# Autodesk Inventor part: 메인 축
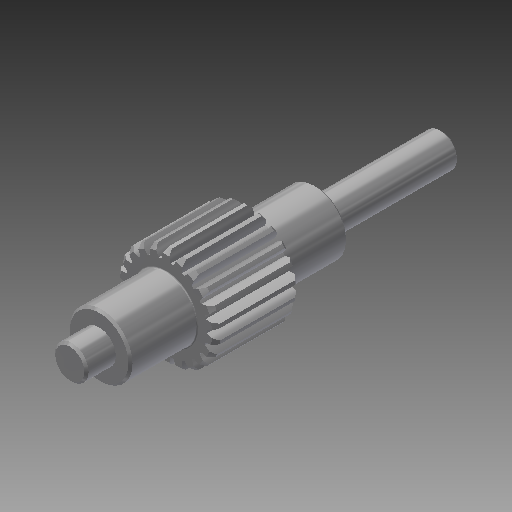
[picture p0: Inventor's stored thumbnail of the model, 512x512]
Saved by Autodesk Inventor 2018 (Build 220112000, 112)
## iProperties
Created: 2016-02
Part Number: 메인 축
Material: 강철, 연강
Document SubType Name: Modeling
Categories: <?xml version="1.0" encoding="UTF-16"?> <MemberInstance><Categories><FamilyTemplate><FamilyTemplateParameter ValueType="xs:double" Id="1" ObjectReferenceKey="da
Density: 7.86 g/cm^3
Appearance: 강철
CustomPartVersion: 1
Author: mdu
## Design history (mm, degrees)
sketch "Sketch1"
  geometry: C1 r 12 at (0, 0)
  constraints: 1 centre point
  dimensions: "d0" = 24 diameter of C1 (= da_da)
extrude "Extrusion1" new body sketch "Sketch1" distance "d1" = 20 (= da_b); taper "d2" = 0 deg
workplane "Work Plane2"
feature "피치 지름" dims "d4" = 10, "d5" = 0
workplane "Work Plane8"
workplane "Work Plane9"
chamfer "모따기1" distance "d49" = 1; stored, may be unused: second distance "d50" = 2, angle "d51" = 45 deg
sketch "스케치3"
  geometry: C1 r 7.5 at (0, 0); 1 further point
  constraints: 1 centre point, 1 coincident
  dimensions: "d52" = 15 diameter of C1
extrude "돌출2" join sketch "스케치3" distance "d53" = 16; taper "d54" = 0 deg
sketch "스케치4"
  geometry: C1 r 4 at (0, 0); 1 further point
  constraints: 1 centre point, 1 coincident
  dimensions: "d55" = 8 diameter of C1
extrude "돌출3" join sketch "스케치4" distance "d56" = 7; taper "d57" = 0 deg
sketch "스케치5"
  geometry: C1 r 7.5 at (0, 0) reference; C2 r 7.5 at (0, 0) reference; 1 further point
extrude "돌출4" join sketch "스케치5" distance "d62" = 16; taper "d63" = 0 deg
sketch "스케치6"
  geometry: C1 r 4 at (0, 0); 1 further point
  constraints: 1 centre point, 1 coincident
  dimensions: "d64" = 8 diameter of C1
extrude "돌출5" join sketch "스케치6" distance "d65" = 30; taper "d66" = 0 deg
chamfer "모따기2" distance "d58" = 0.5; stored, may be unused: second distance "d59" = 2, angle "d60" = 45 deg
fillet "모깎기1" dims "d61" = 0.3
feature "스퍼 기어" dims "d34" = 1.428 (computed from da_z), "da_b" = 20, "da_d" = 22, "da_aw" = 31, "da_da" = 24, "da_df" = 19.5, "da_dw" = 22, angle "da_beta" = 0 deg, "da_lefttooth" = 0, "da_righttooth" = 0
body "Solid1"
sketch "Sketch2"
  geometry: C1 r 12 at (0, 0) reference; C2 r 11 at (0, 0)
  constraints: 1 centre point, 1 coincident
  dimensions: "d3" = 22 diameter of C2 (= da_dw)
body "Srf1"
node "투영된 루프1"
other parameters: "d16" = 31 (= da_aw), "d17" = 0, "d39" = 0, "d41" = 0, "d43" = 31 (= da_aw), "d46" = 31 (= da_aw), "d47" = 0, "d48" = 0
